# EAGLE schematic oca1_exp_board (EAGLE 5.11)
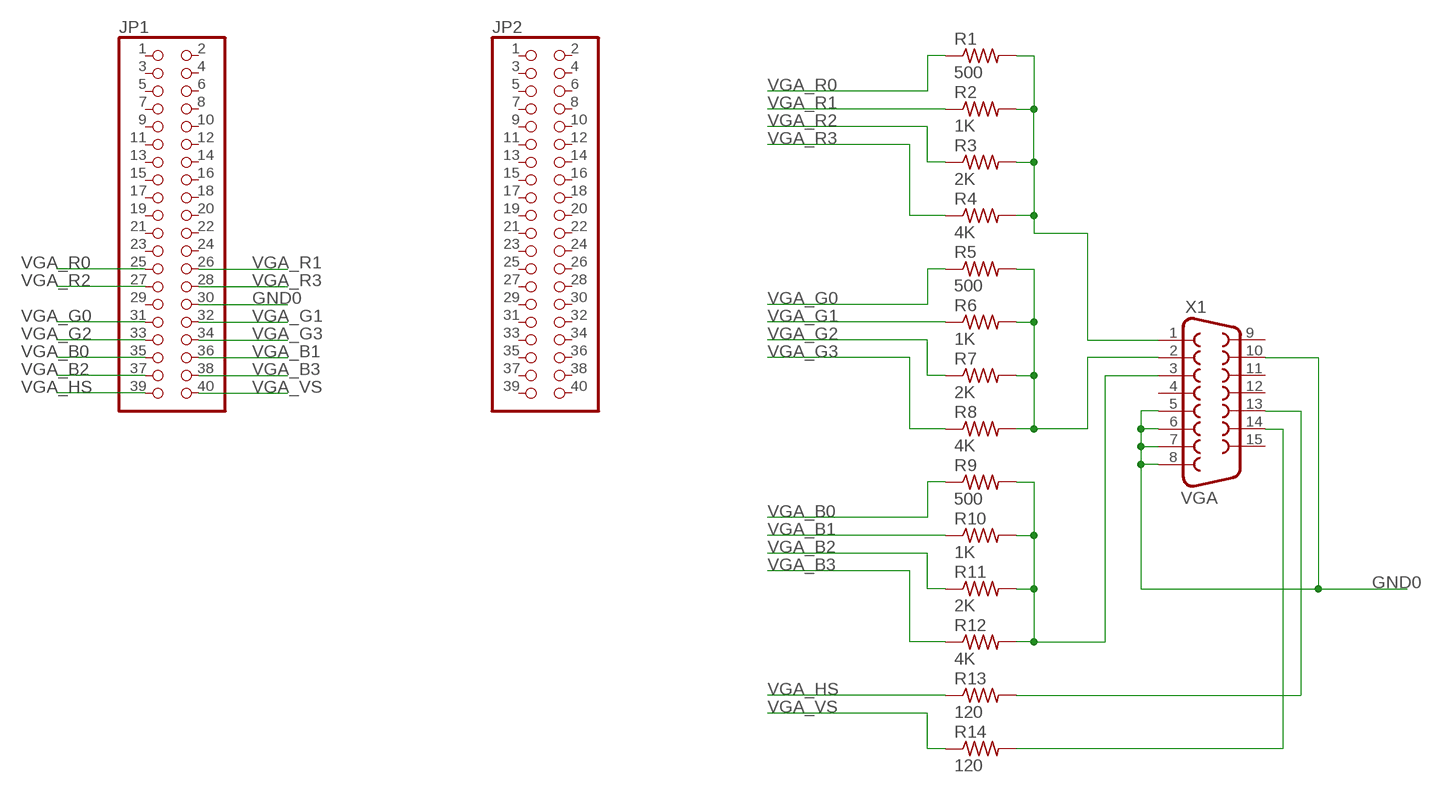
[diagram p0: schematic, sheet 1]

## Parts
JP1  PINHD-2X20  [2X20]
JP2  PINHD-2X20  [2X20]
R1  500  R-US_0207/10  [0207/10]
R2  1K  R-US_0207/10  [0207/10]
R3  2K  R-US_0207/10  [0207/10]
R4  4K  R-US_0207/10  [0207/10]
R5  500  R-US_0207/10  [0207/10]
R6  1K  R-US_0207/10  [0207/10]
R7  2K  R-US_0207/10  [0207/10]
R8  4K  R-US_0207/10  [0207/10]
R9  500  R-US_0207/10  [0207/10]
R10  1K  R-US_0207/10  [0207/10]
R11  2K  R-US_0207/10  [0207/10]
R12  4K  R-US_0207/10  [0207/10]
R13  120  R-US_0207/10  [0207/10]
R14  120  R-US_0207/10  [0207/10]
X1  VGA  F15HDH  [HDF15H]

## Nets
GND0: JP1.30 X1.5 X1.6 X1.7 X1.8 X1.10
N$7: R13.2 X1.13
N$9: R14.2 X1.14
N$10: R5.2 R6.2 R7.2 R8.2 X1.2
N$11: R1.2 R2.2 R3.2 R4.2 X1.1
N$12: R9.2 R10.2 R11.2 R12.2 X1.3
VGA_B0: JP1.35 R9.1
VGA_B1: JP1.36 R10.1
VGA_B2: JP1.37 R11.1
VGA_B3: JP1.38 R12.1
VGA_G0: JP1.31 R5.1
VGA_G1: JP1.32 R6.1
VGA_G2: JP1.33 R7.1
VGA_G3: JP1.34 R8.1
VGA_HS: JP1.39 R13.1
VGA_R0: JP1.25 R1.1
VGA_R1: JP1.26 R2.1
VGA_R2: JP1.27 R3.1
VGA_R3: JP1.28 R4.1
VGA_VS: JP1.40 R14.1
Unconnected: JP1.1 JP1.2 JP1.3 JP1.4 JP1.5 JP1.6 JP1.7 JP1.8 JP1.9 JP1.10 JP1.11 JP1.12 JP1.13 JP1.14 JP1.15 JP1.16 JP1.17 JP1.18 JP1.19 JP1.20 JP1.21 JP1.22 JP1.23 JP1.24 JP1.29 JP2.1 JP2.2 JP2.3 JP2.4 JP2.5 JP2.6 JP2.7 JP2.8 JP2.9 JP2.10 JP2.11 JP2.12 JP2.13 JP2.14 JP2.15 JP2.16 JP2.17 JP2.18 JP2.19 JP2.20 JP2.21 JP2.22 JP2.23 JP2.24 JP2.25 JP2.26 JP2.27 JP2.28 JP2.29 JP2.30 JP2.31 JP2.32 JP2.33 JP2.34 JP2.35 JP2.36 JP2.37 JP2.38 JP2.39 JP2.40 X1.4 X1.9 X1.11 X1.12 X1.15

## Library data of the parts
JP1 JP2 = pinhead:PINHD-2X20: PIN HEADER
R1-R14 = resistor:R-US_: RESISTOR, American symbol
X1 = con-subd:F15: SUB-D; OC_FARNELL: unknown; OC_NEWARK: unknown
